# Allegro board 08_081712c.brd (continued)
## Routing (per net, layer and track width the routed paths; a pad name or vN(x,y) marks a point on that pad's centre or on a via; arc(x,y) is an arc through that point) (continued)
GND_FIELD: length 146.9
  L3_SIG w0.508: P2.SH1 249.88,8.46 225.22,8.46 220.42,3.66 214.88,3.66 212.88,5.66 188.34,5.66 185.8,8.2 149.92,8.2 P1.SH2
  BOTTOM w0.508: P1.14 143.04,14.18 ; P1.14 142.12,15.1 ; P1.14 141.19,14.18 ; P1.SH1 129.83,2.88 ; P1.SH1 127.09,2.88 ; P1.SH1 128.46,4.25 ; P2.13 258.86,14.18 ; P2.13 257.93,15.1 ; P2.13 257.01,14.18 ; 143.22,2.88 P1.SH2 ; P1.SH2 145.96,2.88 ; P1.SH2 144.59,4.25 ; P2.14 269.12,15.1 ; P2.14 268.19,14.18 ; P2.14 270.04,14.18 ; 270.22,2.88 P2.SH2 ; P2.SH2 271.59,4.25 ; P2.SH2 272.96,2.88 ; P1.13 130.93,15.1 ; P1.13 131.86,14.18 ; P1.13 130.01,14.18 ; 254.09,2.88 P2.SH1 ; P2.SH1 256.83,2.88 ; P2.SH1 255.46,4.25
VBUS_DETECT: length 12.2
  L8_SIG w0.114: v1(204.21,12.87) 204.21,17.45 204.98,18.22 204.98,18.99 204.77,19.19 204.77,21.04 v2(205.05,21.31)
  BOTTOM w0.305: R481.2 R482.1 204.03,11.82 C345.1
  BOTTOM w0.508: C345.1 v1(204.21,12.87)
VDDIO: length 251
  TOP w0.127: v1(233.95,29.59) 233.96,29.59 234.68,28.87 U66.5
  TOP w0.14: DS23.A v1(228.74,30.45) ; R549.1 v1(240.09,28.37) ; R551.1 v1(232.09,26.47) ; C430.1 v1(188.33,84.68)
  TOP w0.254: U52.16 238.92,90.52 239.15,90.75 239.15,91.12 ; 239.15,84.01 239.15,83.64 238.92,83.41 U15.16 ; 239.15,98.62 239.15,98.24 238.92,98.02 U14.16
  TOP w0.305: C23.1 210.88,89.33 U9.14 ; U75.14 377.64,24.97 C381.1 ; C11.1 262.24,119.07 U51.21 ; C376.1 9.97,24.97 U74.14 ; U8.21 34.28,113.99 C10.1
  TOP w0.381: R434.2 v1(191.13,90.09) ; R436.2 v1(191.13,105.4) ; R432.2 v1(191.13,97.96)
  TOP w0.508: 239.15,98.62 C72.1 v1(238.4,99.06) ; R531.1 v1(205.99,70.8) ; R555.1 v1(336.32,39.47) ; U44.1 341.91,37.81 341.9,37.82 C280.1 C282.1 v1(341.9,39.75) ; R31.1 v1(34.29,109.27) ; v1(214.27,61.92) C9.1 S11.1 ; v1(264.11,119.05) C13.1 C11.1 ; C377.1 v1(16.39,23.9) ; 386.21,113.79 TP16.1 ; TP16.1 386.21,115.57 ; TP16.1 387.98,113.79 ; TP16.1 387.98,115.57 ; C92.1 v1(228.08,109.83) ; R511.2 R510.2 R509.2 v1(23.87,115.51) ; R511.2 v1(23.87,113.22) ; R511.2 R512.2 R513.2 v1(23.87,110.93) ; C263.1 v1(299.46,109.83) ; R435.2 v1(335.98,90.94) ; C170.1 v1(124.2,102.32) ; U42.1 78.99,37.84 78.99,37.85 C271.1 C273.1 v1(78.99,39.78) ; C10.1 C12.1 v1(36.14,113.97) ; R120.1 v1(226,91.43) ; C23.1 v1(211.34,90.7) ; R437.2 v1(335.98,106.69) ; R517.1 v1(385.13,80.78) ; R535.1 v1(84.96,39.5) ; C16.2 103.75,83.59 v1(102.89,83.59) ; v1(93.08,39.78) C272.1 C270.1 93.08,37.85 93.09,37.84 U41.1 ; R32.1 v1(262.25,114.82) ; R433.2 v1(335.98,98.81) ; C168.1 v1(112.96,102.32) ; U43.1 356.01,37.81 356,37.82 C281.1 C283.1 v1(356,39.75) ; v1(238.4,84.45) C73.1 239.15,84.01 ; R554.1 v1(333.78,39.47) ; R585.1 v1(209.84,83.57) ; R543.1 v1(347.87,39.47) ; R462.1 v1(219.01,91.31) ; C91.1 v1(305.81,109.83) ; R540.1 v1(73.4,39.5) ; R536.1 v1(87.5,39.5) ; R544.1 v1(350.41,39.47) ; R528.1 v1(204.47,70.8) ; S15.2 142.16,90.24 C8.1 v1(140.08,89.57) ; 239.15,91.12 C26.1 239.15,92.06 v1(239.67,92.58) ; C381.1 v1(377.56,24.1) ; R514.1 v1(69.79,80.78) ; C376.1 v1(9.9,24.1) ; C265.1 v1(221.73,109.83) ; C369.1 v1(384.06,23.9) ; R539.1 v1(70.86,39.5)
  L5_PWR w0.508: 257.43,25.26 P2.17 ; P2.17 256.31,26.38 ; P2.17 258.55,26.38 ; 386.21,113.79 TP16.1 ; TP16.1 386.21,115.57 ; TP16.1 387.98,115.57 ; TP16.1 387.98,113.79 ; 130.43,25.26 P1.17 ; P1.17 130.43,27.49 ; P1.17 131.55,26.38 ; P1.17 129.31,26.38
  BOTTOM w0.14: v1(213.86,41.86) R24.1 ; C428.1 v1(188.33,82.45)
  BOTTOM w0.178: U65.B4 v1(102.89,83.59) ; U65.D1 105.39,87.97 ; U65.E4 107.82,84.09
  BOTTOM w0.203: U1.31 134.28,46.58 133.98,46.87 ; U2.31 261.28,46.58 260.99,46.87 ; U2.25 v1(259.97,43.19) ; v1(132.97,43.19) U1.25 ; 139.06,46.87 138.77,46.58 U1.40 ; 266.06,46.87 265.77,46.58 U2.40 ; C68.1 252.84,41.59 U12.6 ; C34.1 125.84,41.59 U11.6
  BOTTOM w0.254: v1(406.4,107.57) 402.59,107.57 395.48,114.68 TP16.1 ; U39.16 132.55,95.16 132.8,94.91 132.8,94.44 ; U45.16 127.67,79.97 127.9,79.75 127.9,79.38 ; U48.16 271.18,79.97 271.41,79.75 271.41,79.38 ; U46.16 144.18,79.97 144.41,79.75 144.41,79.38 ; U67.16 11.93,33.12 11.68,33.37 C295.1 ; U62.16 263.05,88.1 263.28,87.88 263.28,87.5 ; U40.16 119.93,98.64 119.67,98.89 119.67,99.37 ; 136.28,87.5 136.28,87.88 136.05,88.1 U61.16 ; 254.9,79.38 254.9,79.75 254.67,79.97 U47.16 ; 115.28,94.44 115.28,94.91 115.02,95.16 U38.16 ; U69.16 379.6,33.12 379.34,33.37 C382.1
  BOTTOM w0.279: C74.1 306.62,104.48 306.74,104.35 U35.16 ; U36.16 218.99,104.35 218.86,104.48 C266.1 ; U37.16 229.02,104.35 228.89,104.48 C75.1 ; U34.16 296.71,104.35 296.58,104.48 C264.1
  BOTTOM w0.305: R546.1 243.4,25.85 243.09,25.54 U64.5 241.43,25.54 C394.1 ; C7.1 224.26,41.4 223.81,41.86 U7.14 ; R548.1 v1(239.99,24.24) ; R547.1 v1(247.56,24.89)
  BOTTOM w0.457: v1(259.97,43.19) v1(259.46,43.19) ; v1(132.46,43.19) v1(132.97,43.19)
  BOTTOM w0.508: 107.82,84.09 107.82,84.09 C15.2 v1(110.39,84.09) ; 271.41,79.38 C293.1 v1(270.66,78.93) ; v1(265.24,56.13) R86.2 R84.2 R103.2 R98.2 259.72,56.13 v1(259.28,56.57) ; R94.2 v1(254.88,41.85) ; R94.2 R113.1 R108.2 R106.2 ; R94.2 R110.1 v1(254.88,40.77) ; U76.4 150.69,82.86 150.18,82.35 C370.1 v1(149.22,83.06) ; v1(138.24,56.13) R54.2 R52.2 R71.2 R66.2 v1(132.4,56.13) ; C394.1 v1(241.42,26.31) ; v1(114.66,94.12) C267.1 115.28,94.44 ; 260.99,46.87 260.72,47.13 C61.1 C59.1 v1(260.72,49.27) 260.72,49.29 v1(260.35,49.66) ; R563.1 v1(283.01,71.89) ; v1(135.53,87.06) C371.1 136.28,87.5 ; C5.1 v1(163.45,30.2) U5.5 ; C382.1 v1(379.34,34.95) ; v1(143.66,78.93) C291.1 144.41,79.38 ; C75.1 v1(228.89,106.19) ; R2.1 v1(150.29,71.89) ; R62.2 R78.1 v1(127.88,40.77) ; R62.2 R81.1 R76.2 R74.2 ; R62.2 v1(127.88,41.85) ; R15.1 v1(292.02,23.19) ; R92.2 R90.2 v1(255.64,51.24) ; R589.1 v1(150.62,77.35) ; 263.28,87.5 C372.1 v1(262.53,87.06) ; R3.1 v1(151.43,71.89) ; R558.1 v1(277.29,71.89) ; R7.1 v1(156.01,71.89) ; R588.1 v1(152.65,77.35) ; R561.1 v1(280.72,71.89) ; C6.1 v1(290.45,30.2) U6.5 ; v1(139.7,49.66) 139.33,49.29 v1(139.33,49.27) C32.1 C42.1 139.33,47.13 139.06,46.87 ; C34.1 v1(126.78,41.74) ; 133.98,46.87 133.72,47.13 C35.1 C33.1 v1(133.72,49.27) 133.72,49.29 v1(133.35,49.66) ; R529.1 v1(279.65,77.27) ; C68.1 v1(253.78,41.74) ; 132.8,94.44 C268.1 v1(132.18,94.12) ; C74.1 v1(306.62,106.19) ; v1(254.15,78.93) C292.1 254.9,79.38 ; R60.2 R58.2 v1(128.64,51.24) ; R33.1 v1(104.39,92.14) ; R530.1 v1(277.62,77.27) ; R560.1 v1(279.58,71.89) ; v1(127.15,78.93) C290.1 127.9,79.38 ; 105.39,87.97 105.39,89.23 C14.2 v1(105.4,90.03) ; R16.1 v1(288.87,23.19) ; v1(276.23,83.06) C24.1 277.18,82.35 277.69,82.86 U10.4 ; R14.1 v1(161.87,23.19) ; C266.1 v1(218.86,106.19) ; C295.1 v1(11.68,34.95) ; C264.1 v1(296.58,106.19) ; R5.1 v1(153.72,71.89) ; v1(120.29,99.68) C269.1 119.67,99.37 ; R562.1 v1(281.86,71.89) ; R21.1 v1(226.19,42.51) ; R13.1 v1(165.02,23.19) ; R6.1 v1(154.86,71.89) ; v1(266.7,49.66) 266.33,49.29 v1(266.33,49.27) C58.1 C60.1 266.33,47.13 266.06,46.87 ; v1(224.29,40.59) C7.1 ; R50.1 v1(99.18,88.79) ; C169.1 v1(120.59,102.32) ; R559.1 v1(278.43,71.89) ; R35.1 v1(99.18,82.41) ; R4.1 v1(152.58,71.89)
  vias: v1(145.15,35.94) v1(145.91,35.94) v1(146.67,36.07) v1(147.44,36.07) v1(182.33,121.72) v1(238.05,30.73) v1(272.1,35.9) v1(272.86,35.9) v1(273.63,36.16) v1(274.39,36.16) v1(384.81,114.94) v1(384.81,114.3) v1(385.44,114.94) v1(385.44,114.3)
24.576MHZ: length 96.9
  TOP w0.127: v1(176.92,130.18) S16.4A S16.3A R126.2
  BOTTOM w0.127: v1(176.92,130.18) 164.34,130.18 143.97,109.8 98.4,109.8 97.33,110.87 P36.1
24.576MHZ_SOMA: length 2.9
  TOP w0.127: U81.2 180.52,126.19 R502.2
24.576MHZ_SOMB: length 2.9
  TOP w0.127: U81.3 180.12,126.2 R503.2
_N11: length 2.1
  TOP w0.127: R83.1 132.97,28.5 P1.18
_N12: length 1.8
  BOTTOM w0.14: U1.10 140.05,41.19 R57.2
_N13: length 6.8
  BOTTOM w0.14: R70.2 137.41,51.31 136.28,50.17 U1.35
_N14: length 6.7
  BOTTOM w0.14: U1.34 135.77,50.94 136.4,51.56 136.4,52.46 R65.2
_N15: length 2.1
  TOP w0.127: R82.1 140.08,28.5 P1.19
_N16: length 6.8
  BOTTOM w0.14: R73.2 129.54,47.2 129.68,47.06 129.85,47.06 129.99,46.92 129.99,46.62 129.85,46.48 129.68,46.48 129.54,46.34 129.54,45.99 129.68,45.85 130.68,45.85 131.34,45.19 U1.29
_N17: length 6.8
  BOTTOM w0.14: R69.2 130.68,46.61 130.9,46.39 131.13,46.39 131.48,46.74 131.67,46.74 131.8,46.61 131.8,45.97 131.96,45.82 132.18,45.82 132.33,45.97 132.33,46.63 132.47,46.77 132.83,46.77 132.97,46.63 132.97,45.85 133.13,45.69 U1.30
_N18: length 6.9
  BOTTOM w0.14: R64.2 133.6,51.18 134.77,50.01 U1.32
_N19: length 6.8
  BOTTOM w0.14: U1.33 135.28,50.91 134.62,51.56 134.62,52.46 R63.2
_N20: length 17.4
  TOP w0.508: P1.6 142.65,21.3 ; P1.6 141.6,22.35 ; P1.6 141.6,20.24 ; 127.63,20.69 C37.1 ; C37.1 128.17,21.27 ; C37.1 127.63,21.86 ; 145.36,23.23 C40.1 ; C40.1 145.36,24.4 ; C40.1 144.81,23.81 ; 130.44,22.78 P1.7 129.38,23.84 ; 143.67,23.84 P1.12 142.62,22.78 ; 145.36,20.69 C41.1 ; C41.1 144.81,21.27 ; C41.1 145.36,21.86 ; 127.63,23.23 C39.1 ; C39.1 128.17,23.81 ; C39.1 127.63,24.4 ; P1.1 131.45,22.35 ; P1.1 131.45,20.24 ; P1.1 130.4,21.3
_N41: length 2.1
  TOP w0.127: P2.18 259.97,28.5 R115.1
_N42: length 1.8
  BOTTOM w0.14: U2.10 267.05,41.19 R89.2
_N43: length 6.8
  BOTTOM w0.14: U2.35 263.28,50.17 264.41,51.31 R102.2
_N44: length 6.7
  BOTTOM w0.14: U2.34 262.77,50.94 263.4,51.56 263.4,52.46 R97.2
_N45: length 2.1
  TOP w0.127: P2.19 267.08,28.5 R114.1
_N46: length 6.8
  BOTTOM w0.14: U2.29 258.34,45.19 257.68,45.85 256.68,45.85 256.54,45.99 256.54,46.34 256.68,46.48 256.85,46.48 256.99,46.62 256.99,46.92 256.85,47.06 256.68,47.06 256.54,47.2 R105.2
_N47: length 6.8
  BOTTOM w0.14: U2.30 260.13,45.69 259.97,45.85 259.97,46.63 259.83,46.77 259.47,46.77 259.33,46.63 259.33,45.97 259.18,45.82 258.96,45.82 258.8,45.97 258.8,46.61 258.67,46.74 258.48,46.74 258.13,46.39 257.9,46.39 257.68,46.61 R101.2
_N48: length 6.9
  BOTTOM w0.14: U2.32 261.77,50.01 260.6,51.18 R96.2
_N49: length 6.8
  BOTTOM w0.14: U2.33 262.28,50.91 261.62,51.56 261.62,52.46 R95.2
_N50: length 17.4
  TOP w0.508: 269.62,22.78 P2.12 270.67,23.84 ; 272.36,23.23 C65.1 ; C65.1 272.36,24.4 ; C65.1 271.81,23.81 ; C66.1 254.63,21.86 ; C66.1 254.63,20.69 ; C66.1 255.17,21.27 ; 256.38,23.84 P2.7 257.44,22.78 ; 254.63,23.23 C67.1 ; C67.1 255.17,23.81 ; C67.1 254.63,24.4 ; 271.81,21.27 C63.1 ; C63.1 272.36,21.86 ; C63.1 272.36,20.69 ; 268.6,20.24 P2.6 ; P2.6 268.6,22.35 ; P2.6 269.65,21.3 ; 257.4,21.3 P2.1 ; P2.1 258.45,22.35 ; P2.1 258.45,20.24
_N448: length 77.2
  L8_SIG w0.127: v1(289.31,32.77) 287.84,34.24 226.47,34.24 221.14,39.57 v1(221.14,43.16)
  BOTTOM w0.127: R20.2 v1(289.31,32.77)
  BOTTOM w0.14: U7.12 v1(221.14,43.16)
_N450: length 9.5
  BOTTOM w0.127: R11.1 293.76,23.24 300.24,23.24 PB3.3
_N451: length 2.2
  BOTTOM w0.127: R12.1 288.01,23.65 PB4.3
_N452: length 2
  BOTTOM w0.127: R20.1 289.5,30.68 U6.4
_N453: length 2
  BOTTOM w0.127: R19.1 291.4,30.68 U6.6
_N454: length 3.9
  BOTTOM w0.127: U6.1 291.11,26.12 291.11,25.55 290.96,25.4 C3.1 R15.2 R11.2
_N455: length 3.9
  BOTTOM w0.127: U6.3 289.79,26.12 289.79,25.55 289.94,25.4 C4.1 R16.2 R12.2
_N552: length 3.3
  TOP w0.508: C137.P 275.64,142.15 R203.2
_N554: length 3.3
  TOP w0.508: R204.2 267.66,142.15 C138.P
_N555: length 5.6
  TOP w0.508: R194.1 C130.N
_N556: length 5.6
  TOP w0.508: R188.1 C129.N
_N557: length 3.3
  TOP w0.508: R173.2 334.32,142.15 C121.P
_N558: length 5.6
  TOP w0.508: R166.1 C116.N
_N559: length 3.3
  TOP w0.508: C122.P 326.34,142.15 R174.2
_N560: length 3.3
  TOP w0.508: C123.P 315.27,142.15 R175.2
_N561: length 3.3
  TOP w0.508: R176.2 307.29,142.15 C124.P
_N562: length 5.6
  TOP w0.508: R160.1 C115.N
_N563: length 3.3
  TOP w0.508: C135.P 294.69,142.15 R201.2
_N566: length 3.3
  TOP w0.508: R202.2 286.71,142.15 C136.P
_N568: length 3.4
  TOP w0.508: R189.2 287.77,151.97 R190.2 288.16,150.74 U24.5
_N569: length 6.7
  TOP w0.508: R198.1 285.56,148.21 U24.6 ; R198.1 283.61,148.52 C132.1 ; R198.1 R188.2
_N570: length 8.2
  TOP w0.508: C133.2 278.74,145.35 R199.2 276.8,145.67 U25.1 272.92,145.67 272.42,145.16 R203.1
_N571: length 8.5
  TOP w0.508: R192.2 274.58,151.97 R193.2 272.54,151.13 272.18,150.77 272.18,148.57 272.54,148.21 U25.3
_N572: length 7.9
  TOP w0.508: R199.1 278.74,147.25 C133.1 ; R199.1 276.8,146.94 U25.2 ; R199.1 R191.2
_N574: length 3.4
  TOP w0.508: R195.2 268.72,151.97 R196.2 269.11,150.74 U25.5
_N575: length 6.7
  TOP w0.508: U25.6 266.51,148.21 R200.1 ; R200.1 R194.2 ; R200.1 264.56,148.52 C134.1
_N577: length 7.9
  TOP w0.508: C117.1 337.42,147.25 R169.1 ; R169.1 R157.2 ; R169.1 335.47,146.94 U22.2
_N578: length 8.5
  TOP w0.508: R158.2 333.26,151.97 R159.2 331.22,151.13 330.86,150.77 330.86,148.57 331.22,148.21 U22.3
_N580: length 3.4
  TOP w0.508: R161.2 327.4,151.97 R162.2 327.79,150.74 U22.5
_N581: length 6.7
  TOP w0.508: U22.6 325.18,148.21 R170.1 ; R170.1 323.24,148.52 C118.1 ; R170.1 R160.2
_N582: length 8.2
  TOP w0.508: R175.1 312.04,145.16 312.55,145.67 U23.1 316.42,145.67 R171.2 318.37,145.35 C119.2
_N583: length 8.5
  TOP w0.508: R164.2 314.21,151.97 R165.2 312.17,151.13 311.81,150.77 311.81,148.57 312.17,148.21 U23.3
_N584: length 7.9
  TOP w0.508: R171.1 316.42,146.94 U23.2 ; R171.1 R163.2 ; R171.1 318.37,147.25 C119.1
_N586: length 3.4
  TOP w0.508: R167.2 308.35,151.97 R168.2 308.74,150.74 U23.5
_N587: length 6.7
  TOP w0.508: R172.1 R166.2 ; R172.1 306.13,148.21 U23.6 ; R172.1 304.19,148.52 C120.1
_N588: length 8.2
  TOP w0.508: R201.1 291.47,145.16 291.97,145.67 U24.1 295.85,145.67 R197.2 297.79,145.35 C131.2
_N589: length 8.5
  TOP w0.508: R186.2 293.63,151.97 R187.2 291.59,151.13 291.23,150.77 291.23,148.57 291.59,148.21 U24.3
_N590: length 7.9
  TOP w0.508: R197.1 295.85,146.94 U24.2 ; R197.1 R185.2 ; R197.1 297.79,147.25 C131.1
_N672: length 3.3
  TOP w0.508: R259.2 197.92,142.15 C165.P
_N674: length 3.3
  TOP w0.508: R260.2 189.94,142.15 C166.P
_N675: length 5.6
  TOP w0.508: R250.1 C158.N
_N676: length 5.6
  TOP w0.508: R244.1 C157.N
_N677: length 3.3
  TOP w0.508: R229.2 256.59,142.15 C149.P
_N678: length 5.6
  TOP w0.508: R222.1 C144.N
_N679: length 3.3
  TOP w0.508: R230.2 248.61,142.15 C150.P
_N680: length 3.3
  TOP w0.508: R231.2 237.54,142.15 C151.P
_N681: length 3.3
  TOP w0.508: C152.P 229.56,142.15 R232.2
_N682: length 5.6
  TOP w0.508: R216.1 C143.N
_N683: length 3.3
  TOP w0.508: R257.2 216.97,142.15 C163.P
_N686: length 3.3
  TOP w0.508: R258.2 208.99,142.15 C164.P
_N688: length 3.4
  TOP w0.508: U28.5 210.44,150.74 R246.2 210.05,151.97 R245.2
_N689: length 6.7
  TOP w0.508: U28.6 207.83,148.21 R254.1 ; R254.1 205.89,148.52 C160.1 ; R254.1 R244.2
_N690: length 8.2
  TOP w0.508: R259.1 194.69,145.16 195.2,145.67 U29.1 199.08,145.67 R255.2 201.02,145.35 C161.2
_N691: length 8.5
  TOP w0.508: U29.3 194.82,148.21 194.46,148.57 194.46,150.77 194.82,151.13 R249.2 196.86,151.97 R248.2
_N692: length 7.9
  TOP w0.508: R255.1 199.08,146.94 U29.2 ; R255.1 201.02,147.25 C161.1 ; R255.1 R247.2
_N694: length 3.4
  TOP w0.508: U29.5 191.39,150.74 R252.2 191,151.97 R251.2
_N695: length 6.7
  TOP w0.508: U29.6 188.78,148.21 R256.1 ; R256.1 R250.2 ; R256.1 186.84,148.52 C162.1
_N696: length 8.2
  TOP w0.508: R229.1 253.36,145.16 253.87,145.67 U26.1 257.75,145.67 R225.2 259.69,145.35 C145.2
_N697: length 7.9
  TOP w0.508: R225.1 257.75,146.94 U26.2 ; R225.1 259.69,147.25 C145.1 ; R225.1 R213.2
_N698: length 8.5
  TOP w0.508: R214.2 255.53,151.97 R215.2 253.49,151.13 253.13,150.77 253.13,148.57 253.49,148.21 U26.3
_N700: length 3.4
  TOP w0.508: U26.5 250.06,150.74 R218.2 249.67,151.97 R217.2
_N701: length 6.7
  TOP w0.508: R226.1 R216.2 ; R226.1 247.46,148.21 U26.6 ; R226.1 245.51,148.52 C146.1
_N702: length 8.2
  TOP w0.508: C147.2 240.64,145.35 R227.2 238.7,145.67 U27.1 234.82,145.67 234.31,145.16 R231.1
_N703: length 8.5
  TOP w0.508: U27.3 234.44,148.21 234.08,148.57 234.08,150.77 234.44,151.13 R221.2 236.48,151.97 R220.2
_N704: length 7.9
  TOP w0.508: R227.1 238.7,146.94 U27.2 ; R227.1 R219.2 ; R227.1 240.64,147.25 C147.1
_N706: length 3.4
  TOP w0.508: R223.2 230.62,151.97 R224.2 231.01,150.74 U27.5
_N707: length 6.7
  TOP w0.508: R228.1 228.41,148.21 U27.6 ; R228.1 226.46,148.52 C148.1 ; R228.1 R222.2
_N708: length 8.2
  TOP w0.508: C159.2 220.07,145.35 R253.2 218.13,145.67 U28.1 214.25,145.67 213.74,145.16 R257.1
_N709: length 8.5
  TOP w0.508: U28.3 213.87,148.21 213.51,148.57 213.51,150.77 213.87,151.13 R243.2 215.91,151.97 R242.2
_N710: length 7.9
  TOP w0.508: R253.1 220.07,147.25 C159.1 ; R253.1 218.13,146.94 U28.2 ; R253.1 R241.2
_N761: length 3.2
  TOP w0.305: R438.1 395.99,152.74 396.3,153.04 U49.4
_N762: length 3
  TOP w0.305: U49.3 395.41,153.54 C294.1
_N764: length 3.5
  TOP w0.305: U49.7 403.3,153.04 403.61,152.74 C301.1
_N765: length 7.2
  TOP w0.305: C304.1 406.9,150.37 R446.1 405.38,150.5 402.07,150.5 R444.1 401.52,151.05 U49.6
_N766: length 3.2
  TOP w0.305: R442.1 403.99,153.54 U49.8
_N778: length 7.8
  TOP w0.305: U33.24 103.85,112.81 103.5,112.46 103.5,111.63
  TOP w0.508: 103.5,111.63 103.5,109.86 103.89,109.48 R284.2 Q1.1
_N780: length 25.3
  TOP w0.203: C174.2 97.77,117.75 C175.1 R280.2
  TOP w0.305: 101.22,111.31 101.85,111.94 102.27,111.94 103.2,112.88 U33.23 ; U33.41 v1(117.04,115.49) ; U33.20 v1(99.11,115.49) ; C174.2 98.69,117.61 99.17,118.09 U33.16 ; U33.29 v1(107.1,112.7)
  TOP w0.508: Q1.4 Q1.2 v1(102.36,108.81) C179.1 101.73,109.48 101.22,109.99 101.22,111.31 ; C174.2 v1(97.92,116.86)
  BOTTOM w0.508: v1(102.36,108.81) 102.36,107.76 C180.1
_N784: length 5
  TOP w0.305: C181.1 113.6,130.63 U33.62
  TOP w0.508: C181.1 v1(115.6,131.83)
  BOTTOM w0.508: C182.1 115.6,131.1 v1(115.6,131.83)
_N787: length 4.6
  TOP w0.305: C183.1 112.95,131.63 U33.63
  TOP w0.508: C183.1 v1(113.94,131.83)
  BOTTOM w0.508: v1(113.94,131.83) 113.94,131.15 C186.1
_N789: length 3.4
  TOP w0.305: C188.1 99.19,128.99 99.19,128.27 99.62,127.84 U33.1
_N790: length 3.4
  TOP w0.305: C191.1 116.97,128.99 116.97,128.27 116.54,127.84 U33.60
_N791: length 2.6
  TOP w0.305: C193.2 99.29,127.19 U33.2
_N792: length 2.6
  TOP w0.305: U33.59 116.87,127.19 C190.2
_N798: length 2.4
  TOP w0.305: R283.1 117.99,118.74 U33.46
_N799: length 2.6
  TOP w0.305: R282.1 118.11,117.47 117.49,118.09 U33.45
_N800: length 2.5
  TOP w0.305: R278.1 117.67,116.14 U33.42
_N829: length 80.6
  L8_SIG w0.127: v1(221.42,45.11) 222.25,44.28 222.25,39.2 226.71,34.75 289.62,34.75 290.45,33.91 v1(291.59,32.77)
  BOTTOM w0.127: R19.2 v1(291.59,32.77)
  BOTTOM w0.14: U7.9 v1(221.42,45.11)
_N831: length 1.9
  TOP w0.14: R359.1 v1(87.38,23.5) R358.2
  BOTTOM w0.508: C278.1 v1(87.38,23.5)
_N832: length 36
  TOP w0.14: R359.2 U41.12
  TOP w0.254: v1(84.54,6.33) 84.54,8.09 88.01,11.56 90.68,11.56 93.09,13.97 93.09,17.91 88.77,22.23 88.77,24.25 88.52,24.5 R359.2
  BOTTOM w0.305: P18.1_7 79.11,6.73 82.91,6.73 83.36,7.18 84.54,7.18 D5.2 v1(84.54,6.33)
_N833: length 32
  TOP w0.14: R358.1 U41.11
  TOP w0.254: R358.1 86.23,24.5 85.98,24.25 85.98,21.59 88.26,19.3 89.92,19.3 91.83,17.39 91.83,14.74 90.04,12.95 87.58,12.95 85.07,10.44 v1(84.54,9.92)
  BOTTOM w0.305: v1(84.54,9.92) D5.1 83.36,9.07 82.91,9.52 80.55,9.52 P18.1_2
_N836: length 5.7
  TOP w0.14: R356.1 82.93,27.79 83.44,28.3 84.96,28.3 85.47,27.79 U41.10
_N863: length 1.9
  TOP w0.14: R360.2 v1(73.28,23.5) R361.1
  BOTTOM w0.508: C279.1 v1(73.28,23.5)
_N864: length 32.6
  TOP w0.14: R361.2 U42.12
  TOP w0.254: R361.2 74.43,24.5 74.68,24.26 74.68,21.59 75.31,20.96 83.82,20.96 85.85,18.92 85.85,14.37 v1(84.54,13.07)
  BOTTOM w0.305: v1(84.54,13.07) D6.2 83.36,13.92 82.91,13.46 79.14,13.46 P18.2_7
_N865: length 28.5
  TOP w0.14: R360.1 U42.11
  TOP w0.254: v1(84.54,16.65) 84.54,18.33 83.31,19.56 73.41,19.56 71.88,21.08 71.88,24.25 72.14,24.5 R360.1
  BOTTOM w0.305: P18.2_2 80.55,16.28 82.91,16.28 83.39,15.8 D6.1 v1(84.54,16.65)
_N866: length 2.8
  BOTTOM w0.305: P18.2_9 69.46,14.83 R363.2
_N867: length 5.7
  TOP w0.14: R357.1 68.83,27.79 69.34,28.3 70.87,28.3 71.37,27.79 U42.10
_N873: length 2.8
  BOTTOM w0.305: R362.2 69.48,8.08 P18.1_9
_N894: length 1.9
  TOP w0.14: R366.2 v1(350.29,23.48) R367.1
  BOTTOM w0.508: C288.1 v1(350.29,23.48)
_N895: length 36
  TOP w0.14: R367.2 U43.12
  TOP w0.254: v1(347.46,6.31) 347.46,8.06 350.93,11.53 353.59,11.53 356.01,13.94 356.01,17.88 351.69,22.2 351.69,24.22 351.43,24.48 R367.2
  BOTTOM w0.305: P19.1_7 342.03,6.7 345.82,6.7 346.27,7.16 347.46,7.16 D7.2 v1(347.46,6.31)
_N896: length 32
  TOP w0.14: R366.1 U43.11
  TOP w0.254: R366.1 349.15,24.48 348.89,24.22 348.89,21.56 351.18,19.28 352.83,19.28 354.74,17.37 354.74,14.71 352.96,12.93 350.5,12.93 347.99,10.42 v1(347.46,9.89)
  BOTTOM w0.305: P19.1_2 343.46,9.5 345.82,9.5 346.28,9.04 D7.1 v1(347.46,9.89)
_N897: length 5.7
  TOP w0.14: U43.10 348.39,27.77 347.88,28.28 346.35,28.28 345.85,27.77 R364.1
_N898: length 1.9
  TOP w0.14: R369.1 v1(336.19,23.48) R368.2
  BOTTOM w0.508: C289.1 v1(336.19,23.48)
_N899: length 32.6
  TOP w0.14: R369.2 U44.12
  TOP w0.254: R369.2 337.35,24.48 337.59,24.23 337.59,21.56 338.23,20.93 346.74,20.93 348.77,18.9 348.77,14.35 v1(347.46,13.04)
  BOTTOM w0.305: P19.2_7 342.05,13.43 345.82,13.43 346.28,13.89 D8.2 v1(347.46,13.04)
_N900: length 28.5
  TOP w0.14: R368.1 U44.11
  TOP w0.254: v1(347.46,16.62) 347.46,18.3 346.23,19.53 336.32,19.53 334.8,21.06 334.8,24.22 335.05,24.48 R368.1
  BOTTOM w0.305: P19.2_2 343.46,16.25 345.82,16.25 346.3,15.77 D8.1 v1(347.46,16.62)
_N901: length 2.8
  BOTTOM w0.305: P19.2_9 332.37,14.81 R371.2
_N902: length 5.7
  TOP w0.14: R365.1 331.75,27.77 332.26,28.28 333.78,28.28 334.29,27.77 U44.10
_N903: length 2.8
  BOTTOM w0.305: R370.2 332.4,8.05 P19.1_9
_N916: length 11.2
  TOP w0.114: R268.1 108.99,106.66 113.68,106.66 114.66,105.68 U30.10
_N917: length 10.9
  TOP w0.114: R270.1 107.31,108.98 109.24,107.06 113.92,107.06 115.06,105.92 U30.9
_N918: length 5.5
  TOP w0.114: R272.1 114.17,107.44 115.46,106.15 U30.8
_N919: length 6.5
  TOP w0.114: U30.7 115.86,106.64 v1(115.44,107.06)
  TOP w0.127: R275.1 v1(113.03,108.71)
  BOTTOM w0.114: v1(115.44,107.06) 113.8,108.71 v1(113.03,108.71)
_N920: length 3.7
  TOP w0.14: R268.2 106.17,112.26 105.8,112.63 U33.27
_N921: length 3.9
  TOP w0.14: R270.2 107.31,111.69 106.45,112.56 U33.28
_N922: length 4
  TOP w0.14: U33.38 112.95,111.7 R272.2
_N923: length 3.8
  TOP w0.14: U33.37 112.3,111.21 R275.2
_N935: length 10.2
  TOP w0.127: R274.1 v1(111.89,108.71)
  BOTTOM w0.114: v1(111.89,108.71) 112.52,108.08 113.67,108.08 115.19,106.55 118.11,106.55 118.89,105.77 U31.10
_N937: length 11.4
  TOP w0.127: R277.1 v1(109.6,108.71)
  BOTTOM w0.114: U31.8 118.09,105.3 117.6,105.79 114.68,105.79 113.16,107.31 110.99,107.31 v1(109.6,108.71)
_N938: length 12
  TOP w0.127: R279.1 v1(108.46,108.71)
  BOTTOM w0.114: v1(108.46,108.71) 110.23,106.93 112.9,106.93 114.43,105.41 117.35,105.41 117.69,105.07 U31.7
_N939: length 18.2
  TOP w0.14: U32.10 125.84,104.92 v1(125.38,105.39) 125.38,106.01 R271.2
  TOP w0.305: U33.43 v1(117.33,116.79)
  L3_SIG w0.127: v1(125.38,105.39) 125.38,107.92 117.98,115.32 117.98,116.14 v1(117.33,116.79)
_N940: length 19.3
  TOP w0.14: U32.9 v1(126.24,105.39) 126.24,106.03 R273.2
  TOP w0.305: U33.44 v1(117.04,117.44)
  L3_SIG w0.127: v1(117.04,117.44) 117.76,117.44 118.87,116.33 118.87,115.57 126.24,108.2 v1(126.24,105.39)
_N942: length 10.8
  TOP w0.127: R276.1 v1(110.74,108.71)
  BOTTOM w0.114: v1(110.74,108.71) 111.76,107.7 113.41,107.7 114.94,106.17 117.86,106.17 118.49,105.54 U31.9
_N943: length 3.6
  TOP w0.14: R274.2 111.65,110.72 U33.36
_N944: length 3.6
  TOP w0.14: U33.35 111,110.74 R276.2
_N945: length 4
  TOP w0.14: R279.2 109.7,111.73 U33.33
_N946: length 3.8
  TOP w0.14: U33.34 110.35,111.23 R277.2
_N948: length 22.3
  TOP w0.14: U32.7 127.04,104.79 127.27,105.03 127.79,105.03 v1(128.14,105.39) R269.2
  TOP w0.305: U33.47 v1(117.04,119.39)
  L3_SIG w0.127: v1(117.04,119.39) 128.14,108.29 v1(128.14,105.39)
_N956: length 3.6
  TOP w0.203: C176.1 97.05,118.61 C174.1 98.05,118.74 U33.15
_N957: length 4.8
  TOP w0.508: C176.2 94.74,118.77 94.23,118.26 94.23,117.22 94.74,116.71 R280.1
_N962: length 7.1
  TOP w0.508: R289.2 133.68,109.56 C203.1 137.56,109.56 C399.1 138.95,109.67 C211.P
_N965: length 4.2
  TOP w0.305: U18.3 297.2,122.92 296.43,123.69
  TOP w0.508: 296.43,123.69 C87.2 295.14,123.7 R151.2
_N982: length 1
  TOP w0.508: C83.2 R151.1
_N983: length 5.5
  TOP w0.305: C79.1 296.84,119.42 U18.10
  TOP w0.508: C79.1 294.88,118.86 C81.1 294.4,118.86 R149.1
_N985: length 10.2
  TOP w0.305: C95.1 296.16,124.84 297.59,123.42 U18.2
  TOP w0.508: C95.1 295.39,124.85 295.03,125.21 C99.1 291.95,125.21 C103.1 291.05,125.32 290.64,124.9 A1.3
_N988: length 3.3
  TOP w0.14: U18.13 299.74,115.81 R145.1
_N989: length 3.5
  TOP w0.14: U18.14 300.24,116.45 R141.1
_N990: length 3.9
  TOP w0.14: R146.1 301.63,116.2 301.37,116.2 300.74,116.84 U18.15
_N991: length 4.4
  TOP w0.14: U18.16 301.24,117.23 302.26,116.2 302.77,116.2 R142.1
_N992: length 3
  TOP w0.14: U20.7 302.3,112.69 303.42,113.8 R142.2
_N993: length 2.7
  TOP w0.14: R146.2 302.27,113.55 301.9,113.18 U20.8
_N994: length 2.7
  TOP w0.14: R141.2 301.13,113.53 301.5,113.16 U20.9
_N995: length 3
  TOP w0.14: U20.10 301.1,112.67 301.08,112.69 301.08,112.71 299.99,113.8 R145.2
_N996: length 12.2
  TOP w0.14: v1(303.02,116.97) 302.25,117.74 302.25,118.05 302.24,118.06 U18.18 ; U16.8 308.25,113.04 v1(308.99,113.79) R127.2
  BOTTOM w0.203: v1(303.02,116.97) 304.8,115.19 307.59,115.19 v1(308.99,113.79)
_N997: length 14.8
  TOP w0.14: U18.17 301.74,117.44 v1(302.24,116.95) ; U16.7 308.65,112.3 v1(310.13,113.79) R129.2
  BOTTOM w0.203: v1(310.13,113.79) 308.22,115.7 305.05,115.7 303.28,117.47 302.77,117.47 v1(302.24,116.95)
_N998: length 19.2
  TOP w0.14: R131.1 v1(307.85,113.79) U16.9 ; v1(296.16,120.98) 297,120.98 297.44,121.42 U18.6
  BOTTOM w0.203: v1(307.85,113.79) 306.95,114.68 302.46,114.68 v1(296.16,120.98)
_N1002: length 2.9
  TOP w0.14: R133.1 295.24,119.92 U18.9
_N1003: length 3.9
  TOP w0.14: R137.1 303.66,116.46 303.66,117.09 302.74,118.01 U18.19
_N1004: length 4.2
  TOP w0.14: U18.20 303.24,118.27 304.29,117.22 304.29,116.97 R139.1
_N1005: length 3.4
  TOP w0.14: R135.2 295.15,121.08 295.84,120.4 297.05,120.4 297.57,120.92 U18.7
_N1045: length 4.2
  TOP w0.305: U19.3 219.48,122.92 218.7,123.69
  TOP w0.508: 218.7,123.69 C88.2 217.42,123.7 R152.2
_N1046: length 1
  TOP w0.508: C84.2 R152.1
_N1047: length 5.5
  TOP w0.305: U19.10 219.12,119.42 C80.1
  TOP w0.508: R150.1 216.68,118.86 C82.1 217.15,118.86 C80.1
_N1048: length 10.2
  TOP w0.305: C96.1 218.44,124.84 219.87,123.42 U19.2
  TOP w0.508: A2.3 212.91,124.9 213.33,125.32 C104.1 214.23,125.21 C100.1 217.31,125.21 217.67,124.85 C96.1
_N1049: length 3.3
  TOP w0.14: R147.1 222.02,115.81 U19.13
_N1050: length 3.5
  TOP w0.14: R143.1 222.52,116.45 U19.14
_N1051: length 3.9
  TOP w0.14: R148.1 223.91,116.2 223.65,116.2 223.02,116.84 U19.15
_N1052: length 4.4
  TOP w0.14: U19.16 223.52,117.23 224.54,116.2 225.05,116.2 R144.1
_N1053: length 3
  TOP w0.14: U21.7 224.57,112.69 225.69,113.8 R144.2
_N1054: length 2.7
  TOP w0.14: U21.8 224.17,113.18 224.55,113.55 R148.2
_N1055: length 2.7
  TOP w0.14: U21.9 223.77,113.16 223.41,113.53 R143.2
_N1056: length 3
  TOP w0.14: U21.10 223.37,112.67 223.35,112.69 223.35,112.71 222.26,113.8 R147.2
_N1057: length 12.2
  TOP w0.14: v1(225.3,116.97) 224.52,117.74 224.52,118.05 224.52,118.06 U19.18 ; R128.2 v1(231.27,113.79) 230.52,113.04 U17.8
  BOTTOM w0.203: v1(225.3,116.97) 227.08,115.19 229.87,115.19 v1(231.27,113.79)
_N1058: length 14.8
  TOP w0.14: U19.17 224.02,117.44 v1(224.51,116.95) ; R130.2 v1(232.41,113.79) 230.92,112.3 U17.7
  BOTTOM w0.203: v1(224.51,116.95) 225.04,117.47 225.55,117.47 227.33,115.7 230.5,115.7 v1(232.41,113.79)
_N1059: length 19.2
  TOP w0.14: U17.9 v1(230.12,113.79) R132.1 ; U19.6 219.71,121.42 219.27,120.98 v1(218.44,120.98)
  BOTTOM w0.203: v1(218.44,120.98) 224.73,114.68 229.23,114.68 v1(230.12,113.79)
_N1060: length 2.9
  TOP w0.14: U19.9 217.52,119.92 R134.1
_N1061: length 3.9
  TOP w0.14: U19.19 225.02,118.01 225.93,117.09 225.93,116.46 R138.1
_N1062: length 4.2
  TOP w0.14: R140.1 226.57,116.97 226.57,117.22 225.52,118.27 U19.20
_N1063: length 3.4
  TOP w0.14: U19.7 219.85,120.92 219.33,120.4 218.12,120.4 217.43,121.08 R136.2
_N1086: length 7
  TOP w0.203: P36.2 96.89,114.67 R281.2 97.1,115.82 97.79,115.82 99.41,117.44 U33.17
_N1090: length 1.8
  TOP w0.14: R265.2 126.64,101.93 U32.4
_N1095: length 2.2
  TOP w0.14: R123.2 307.45,110.08 U16.2
_N1105: length 7.1
  TOP w0.508: C212.P 138.95,111.47 C399.2 137.56,111.57 C204.1 133.68,111.57 R290.2
_N1117: length 5.9
  TOP w0.127: R392.1 227.08,38.54 R384.2 227.08,38.55 R376.2
_N1122: length 5.9
  TOP w0.127: R377.2 228.22,38.55 R386.2 228.22,38.54 R393.1
_N1134: length 5.9
  TOP w0.127: R372.2 R388.1
_N1138: length 5.9
  TOP w0.127: R373.2 R389.1
_N1142: length 5.9
  TOP w0.127: R374.2 R390.1
_N1146: length 5.9
  TOP w0.127: R375.2 R391.1
_N1196: length 5.9
  TOP w0.127: R382.2 235.46,38.55 R385.2 235.46,38.54 R398.1
_N1197: length 5.9
  TOP w0.127: R399.1 236.61,35.62 R387.2 236.6,38.55 R383.2
_N1198: length 5.9
  TOP w0.127: R378.2 R394.1
_N1199: length 5.9
  TOP w0.127: R379.2 R395.1
_N1200: length 5.9
  TOP w0.127: R380.2 R396.1
_N1201: length 5.9
  TOP w0.127: R381.2 R397.1
_N1233: length 3.3
  TOP w0.127: SOMA.111 v1(141.64,64.78)
  BOTTOM w0.127: R1.2 141.64,62.98 v1(141.64,64.78)
_N1244: length 7.1
  TOP w0.508: R291.2 133.68,118.2 C205.1 137.56,118.2 C400.1 138.95,118.3 C213.P
_N1245: length 7.1
  TOP w0.508: C214.P 138.95,120.1 C400.2 137.56,120.21 C206.1 133.68,120.21 R292.2
_N1250: length 7.1
  TOP w0.508: C207.P 138.95,126.94 C401.1 137.56,126.83 C199.1 133.68,126.83 R285.2
_N1251: length 7.1
  TOP w0.508: C208.P 138.95,128.74 C401.2 137.56,128.84 C200.1 133.68,128.84 R286.2
_N1256: length 7.1
  TOP w0.508: C209.P 138.95,135.57 C402.1 137.56,135.47 C201.1 133.68,135.47 R287.2
_N1257: length 7.1
  TOP w0.508: C210.P 138.95,137.37 C402.2 137.56,137.48 C202.1 133.68,137.48 R288.2
_N1276: length 7.1
  TOP w0.508: C227.P 138.56,153.3 C403.1 138.66,151.91 C219.1 138.66,148.03 R305.2
_N1277: length 7.1
  TOP w0.508: R306.2 136.65,148.03 C220.1 136.65,151.91 C403.2 136.76,153.3 C228.P
_N1278: length 7.1
  TOP w0.508: C229.P 129.92,153.3 C404.1 130.03,151.91 C221.1 130.03,148.03 R307.2
_N1279: length 7.1
  TOP w0.508: R308.2 128.02,148.03 C222.1 128.02,151.91 C404.2 128.12,153.3 C230.P
_N1280: length 7.1
  TOP w0.508: R301.2 121.39,148.03 C215.1 121.39,151.91 C405.1 121.29,153.3 C223.P
_N1281: length 7.1
  TOP w0.508: C224.P 119.49,153.3 C405.2 119.38,151.91 C216.1 119.38,148.03 R302.2
_N1282: length 7.1
  TOP w0.508: C225.P 112.65,153.3 C406.1 112.75,151.91 C217.1 112.75,148.03 R303.2
_N1283: length 7.1
  TOP w0.508: C226.P 110.85,153.3 C406.2 110.74,151.91 C218.1 110.74,148.03 R304.2
_N1300: length 7.1
  TOP w0.508: C243.P 104.01,153.3 C407.1 104.12,151.91 C235.1 104.12,148.03 R321.2
_N1301: length 7.1
  TOP w0.508: C244.P 102.21,153.3 C407.2 102.11,151.91 C236.1 102.11,148.03 R322.2
_N1302: length 7.1
  TOP w0.508: R323.2 95.48,148.03 C237.1 95.48,151.91 C408.1 95.38,153.3 C245.P
_N1303: length 7.1
  TOP w0.508: C246.P 93.58,153.3 C408.2 93.47,151.91 C238.1 93.47,148.03 R324.2
_N1304: length 7.1
  TOP w0.508: C239.P 86.74,153.3 C409.1 86.85,151.91 C231.1 86.85,148.03 R317.2
_N1305: length 7.1
  TOP w0.508: C240.P 84.94,153.3 C409.2 84.84,151.91 C232.1 84.84,148.03 R318.2
_N1306: length 7.1
  TOP w0.508: C241.P 78.11,153.3 C410.1 78.21,151.91 C233.1 78.21,148.03 R319.2
_N1307: length 7.1
  TOP w0.508: R320.2 76.2,148.03 C234.1 76.2,151.91 C410.2 76.31,153.3 C242.P
_N1324: length 7.1
  TOP w0.508: R333.2 82.48,137.48 C247.1 78.59,137.48 C411.1 77.21,137.37 C251.P
_N1325: length 7.1
  TOP w0.508: C252.P 77.21,135.57 C411.2 78.59,135.47 C248.1 82.48,135.47 R334.2
_N1326: length 7.1
  TOP w0.508: R335.2 82.48,128.84 C249.1 78.59,128.84 C412.1 77.21,128.74 C253.P
_N1327: length 7.1
  TOP w0.508: R336.2 82.48,126.83 C250.1 78.59,126.83 C412.2 77.21,126.94 C254.P
_N1336: length 7.1
  TOP w0.508: R341.2 82.48,120.21 C255.1 78.59,120.21 C413.1 77.21,120.1 C259.P
_N1337: length 7.1
  TOP w0.508: C260.P 77.21,118.3 C413.2 78.59,118.2 C256.1 82.48,118.2 R342.2
_N1338: length 7.1
  TOP w0.508: C261.P 77.21,111.47 C414.1 78.59,111.57 C257.1 82.48,111.57 R343.2
_N1339: length 7.1
  TOP w0.508: C262.P 77.21,109.67 C414.2 78.59,109.56 C258.1 82.48,109.56 R344.2
_N1376: length 8.2
  TOP w0.508: R173.1 331.09,145.16 331.6,145.67 U22.1 335.47,145.67 R169.2 337.42,145.35 C117.2
_N1392: length 6.7
  TOP w0.508: S3.1 335.71,157.69 C113.N
_N1393: length 7.3
  TOP w0.508: S3.2 331.78,155.45 335.28,155.45 335.79,154.94 R157.1
_N1395: length 6.7
  TOP w0.508: S4.1 316.66,157.69 C114.N
_N1396: length 7.3
  TOP w0.508: R163.1 316.74,154.94 316.23,155.45 312.73,155.45 S4.2
_N1398: length 6.7
  TOP w0.508: S5.1 296.09,157.69 C127.N
_N1399: length 7.3
  TOP w0.508: R185.1 296.16,154.94 295.66,155.45 292.16,155.45 S5.2
_N1401: length 6.7
  TOP w0.508: C128.N 277.04,157.69 S6.1
_N1402: length 7.3
  TOP w0.508: R191.1 277.11,154.94 276.61,155.45 273.11,155.45 S6.2
_N1404: length 6.7
  TOP w0.508: C141.N 257.99,157.69 S7.1
_N1405: length 7.3
  TOP w0.508: S7.2 254.06,155.45 257.56,155.45 258.06,154.94 R213.1
_N1407: length 6.7
  TOP w0.508: S8.1 238.94,157.69 C142.N
_N1408: length 7.3
  TOP w0.508: R219.1 239.01,154.94 238.51,155.45 235.01,155.45 S8.2
_N1410: length 7.3
  TOP w0.508: R241.1 218.44,154.94 217.93,155.45 214.43,155.45 S9.2
_N1411: length 6.7
  TOP w0.508: C155.N 218.37,157.69 S9.1
_N1413: length 6.7
  TOP w0.508: S10.1 199.32,157.69 C156.N
_N1414: length 7.3
  TOP w0.508: R247.1 199.39,154.94 198.88,155.45 195.38,155.45 S10.2
_N1418: length 1.4
  BOTTOM w0.14: R349.1 295.84,103.85 U34.15
_N1461: length 1.4
  BOTTOM w0.203: R350.1 305.87,103.85 U35.15
_N1496: length 1.4
  BOTTOM w0.14: U36.15 218.12,103.85 R351.1
_N1497: length 1.4
  BOTTOM w0.203: R352.1 228.15,103.85 U37.15
_N1508: length 1.4
  BOTTOM w0.127: R353.1 U38.15
_N1509: length 1.4
  BOTTOM w0.127: U39.15 R354.1
_N1534: length 1.5
  BOTTOM w0.127: U40.15 R355.1
_N1575: length 6.3
  BOTTOM w0.14: R56.1 142.35,41.53 143.82,40.07 143.82,37.91 144.16,37.57 Y1.3
_N1581: length 1.4
  BOTTOM w0.127: U45.15 128.51,80.47 R408.1
_N1583: length 139.3
  L3_SIG w0.127: v1(122.56,80.7) 123.7,79.55 131.83,79.55 133.11,78.27 142.39,78.27 143.01,77.65 146.27,77.65 147.79,79.17 149.7,79.17 149.74,79.22 149.75,79.22 150.51,79.98 154.2,79.98 157.86,83.64 193.32,83.64 196.21,80.75 211.48,80.75 217.8,74.42 239.95,74.42 246.23,80.7 v1(249.55,80.7)
  BOTTOM w0.127: U45.2 122.78,80.47 v1(122.56,80.7) ; v1(249.55,80.7) 249.78,80.47 U47.2
_N1584: length 140.1
  L3_SIG w0.127: v1(249.59,82.23) 247.26,82.23 239.96,74.93 217.91,74.93 211.65,81.19 196.46,81.19 193.62,84.04 157.75,84.04 154.05,80.34 150.37,80.34 149.6,79.57 149.6,79.57 149.55,79.53 147.64,79.53 146.12,78 143.16,78 142.45,78.72 133.27,78.72 132.08,79.91 124.91,79.91 v1(122.59,82.23)
  BOTTOM w0.127: v1(249.59,82.23) 249.85,81.97 U47.5 ; U45.5 122.85,81.97 v1(122.59,82.23)
_N1585: length 141.9
  L3_SIG w0.127: v1(255.09,82.75) 255.09,83.31 253.82,84.58 248.21,84.58 241.45,77.82 224.63,77.82 222.52,75.72 218.29,75.72 211.89,82.12 197.1,82.12 193.47,85.75 187.6,85.75 186.61,84.76 157.39,84.76 153.68,81.05 148.11,81.05 146.97,79.91 145.64,79.91 145.24,79.5 138.42,79.5 138.4,79.49 133.97,79.49 130.71,82.75 v1(128.09,82.75)
  BOTTOM w0.127: v1(128.09,82.75) 127.82,82.47 U45.11 ; U47.11 254.82,82.47 v1(255.09,82.75)
_N1586: length 142.7
  L3_SIG w0.127: v1(255.09,81.22) 254.3,82.01 254.3,83.01 253.21,84.1 248.41,84.1 241.76,77.44 224.75,77.44 222.67,75.36 222.55,75.36 222.5,75.31 218.06,75.31 211.73,81.64 196.67,81.64 192.91,85.39 188.04,85.39 187.05,84.4 157.54,84.4 153.83,80.7 150.22,80.7 149.45,79.93 147.49,79.93 147.11,79.55 145.85,79.55 144.65,78.36 143.31,78.36 142.59,79.07 133.65,79.07 131.5,81.22 v1(128.09,81.22)
  BOTTOM w0.127: v1(128.09,81.22) 127.85,80.97 U45.14 ; U47.14 254.85,80.97 v1(255.09,81.22)
_N1598: length 1.4
  BOTTOM w0.127: U47.15 255.51,80.47 R410.1
_N1602: length 1.4
  BOTTOM w0.127: U45.12 128.53,81.97 R403.2
_N1603: length 1.4
  BOTTOM w0.127: U45.9 128.5,83.47 R402.2
_N1604: length 1.4
  BOTTOM w0.127: R401.2 122.19,82.97 U45.7
_N1605: length 1.4
  BOTTOM w0.127: R400.2 122.17,81.47 U45.4
_N1606: length 1.4
  BOTTOM w0.127: U47.4 249.17,81.47 R412.1
_N1607: length 1.4
  BOTTOM w0.127: U47.7 249.19,82.97 R413.1
_N1608: length 1.4
  BOTTOM w0.127: U47.9 255.5,83.47 R414.1
_N1609: length 1.4
  BOTTOM w0.127: U47.12 255.53,81.97 R415.1
_N1616: length 1.4
  TOP w0.508: R429.1 DS16.C
_N1617: length 1.4
  TOP w0.508: R430.1 DS17.C
_N1618: length 1.4
  TOP w0.508: R431.1 DS18.C
_N1619: length 1.4
  TOP w0.508: R427.1 DS14.C
_N1620: length 1.4
  TOP w0.508: R428.1 DS15.C
_N1621: length 1.4
  TOP w0.508: R426.1 DS13.C
_N1696: length 78.1
  TOP w0.127: S16.8B 166,139.83 164.49,139.83 164.11,139.45 164.11,136.14 164.49,135.76 166,135.76 S16.6B 166,134.75 164.49,134.75 164.11,134.37 164.11,131.06 164.49,130.68 166,130.68 S16.4B 166,129.67 164.49,129.67 164.11,129.29 164.11,125.98 164.49,125.6 166,125.6 S16.2B v1(168.31,125.09)
  TOP w0.14: R136.1 v1(215.51,121.08)
  BOTTOM w0.127: v1(168.31,125.09) 168.95,124.46 179.44,124.46 180.07,123.83 184.77,123.83 187.52,121.08 v1(215.51,121.08)
_N1726: length 1.4
  BOTTOM w0.127: U46.15 145.02,80.47 R409.1
_N1727: length 143.1
  L3_SIG w0.127: v1(139.06,80.7) 139.88,81.52 142.06,81.52 143.73,79.86 145.08,79.86 146.63,81.41 153.53,81.41 157.32,85.19 185.33,85.19 186.28,86.14 190.33,86.14 191.1,86.91 193.33,86.91 197.69,82.55 212.09,82.55 218.57,76.07 222.38,76.07 224.51,78.21 240.92,78.21 247.75,85.04 254.28,85.04 258.62,80.7 v1(266.06,80.7)
  BOTTOM w0.127: U46.2 139.29,80.47 v1(139.06,80.7) ; U48.2 266.29,80.47 v1(266.06,80.7)
_N1728: length 144
  L3_SIG w0.127: v1(266.1,82.23) 258.23,82.23 254.91,85.55 247.6,85.55 240.61,78.56 224.28,78.56 219.82,83.02 198.16,83.02 193.92,87.26 190.95,87.26 190.19,86.5 186.13,86.5 185.18,85.55 157.17,85.55 153.41,81.79 146.51,81.79 144.93,80.21 144.25,80.21 143.59,80.88 143.59,83.11 142.67,84.02 140,84.02 139.1,83.12 v1(139.1,82.23)
  BOTTOM w0.127: U48.5 266.36,81.97 v1(266.1,82.23) ; U46.5 139.36,81.97 v1(139.1,82.23)
_N1729: length 146.9
  L3_SIG w0.127: v1(271.6,82.75) 271.6,85.78 265.1,92.28 248.43,92.28 241.75,85.6 235.64,85.6 229.67,79.63 225.25,79.63 215.39,89.48 186.85,89.48 184.41,87.05 157.05,87.05 153.7,83.69 145.55,83.69 v1(144.6,82.75)
  BOTTOM w0.127: v1(144.6,82.75) 144.33,82.47 U46.11 ; v1(271.6,82.75) 271.33,82.47 U48.11
_N1730: length 144
  L3_SIG w0.127: v1(144.6,81.22) 145.88,82.5 153.09,82.5 157.2,86.61 184.49,86.61 187,89.13 215.04,89.13 224.89,79.27 239.88,79.27 247.27,86.66 254.76,86.66 256.9,88.8 258.63,88.8 261.27,86.16 267.47,86.16 270.94,82.69 270.94,81.88 v1(271.6,81.22)
  BOTTOM w0.127: U46.14 144.36,80.97 v1(144.6,81.22) ; U48.14 271.36,80.97 v1(271.6,81.22)
_N1731: length 1.4
  BOTTOM w0.127: R411.1 272.02,80.47 U48.15
_N1732: length 1.4
  BOTTOM w0.127: R407.2 145.04,81.97 U46.12
_N1733: length 1.4
  BOTTOM w0.127: R406.2 145.01,83.47 U46.9
_N1734: length 1.4
  BOTTOM w0.127: U46.7 138.7,82.97 R405.2
_N1735: length 1.4
  BOTTOM w0.127: R404.2 138.68,81.47 U46.4
_N1736: length 1.4
  BOTTOM w0.127: R416.1 265.68,81.47 U48.4
_N1737: length 1.4
  BOTTOM w0.127: R417.1 265.7,82.97 U48.7
_N1738: length 1.4
  BOTTOM w0.127: R418.1 272.01,83.47 U48.9
_N1739: length 1.4
  BOTTOM w0.127: R419.1 272.04,81.97 U48.12
_N1774: length 1.5
  TOP w0.127: DS1.C R23.1
_N1775: length 1.5
  TOP w0.127: DS2.C R26.1
_N1776: length 1.5
  TOP w0.127: DS3.C R27.1
_N1800: length 1.5
  TOP w0.127: DS4.C R28.1
_N1801: length 1.5
  TOP w0.127: DS5.C R29.1
_N1802: length 1.5
  TOP w0.127: DS6.C R30.1
_N1808: length 3.3
  TOP w0.127: SOMB.111 v1(268.64,64.78)
  BOTTOM w0.127: v1(268.64,64.78) 268.64,62.98 R8.2
_N1810: length 1.5
  BOTTOM w0.14: U1.9 140.07,41.69 140.23,41.53 140.24,41.53 140.24,41.53 R56.2
_N1813: length 6.3
  BOTTOM w0.14: R88.1 269.35,41.53 270.82,40.07 270.82,37.91 271.16,37.57 Y2.3
_N1815: length 1.5
  BOTTOM w0.14: R88.2 267.24,41.53 267.24,41.53 267.23,41.53 267.07,41.69 U2.9
_N1851: length 4
  TOP w0.127: Y3.3 R502.1 R503.1 178.56,127.63 R126.1
_N1863: length 1.4
  TOP w0.127: U14.15 239.76,97.52 R121.1
_N1867: length 1.4
  TOP w0.127: R122.1 239.76,82.91 U15.15
_N1869: length 1.7
  TOP w0.127: R120.2 226.04,89.69 S2.1
_N1910: length 5.3
  BOTTOM w0.14: U65.A3 101.49,85.09 101.09,84.7 101.09,83.69 100.84,83.44 100.58,83.44 100.33,83.69 100.33,84.32 100.19,84.45 R39.2
_N1911: length 5.3
  BOTTOM w0.14: R37.2 103.61,89.02 103.61,88.71 103.43,88.52 102.87,88.52 102.73,88.38 102.73,88.15 102.87,88.01 103.62,88.01 103.87,87.76 103.87,86.23 104.01,86.09 U65.C2
_N1912: length 5.4
  BOTTOM w0.14: U65.C3 103.92,85.56 99.22,85.56 R41.1
_N1913: length 5.3
  BOTTOM w0.14: R43.1 105.46,81.54 105.46,81.86 105.32,82 104.31,82 104.14,82.17 104.14,82.41 104.28,82.55 104.76,82.55 104.9,82.69 104.9,83.6 U65.D4
_N1914: length 5.3
  BOTTOM w0.14: R46.1 106.18,89 106.18,88.71 106.36,88.52 106.92,88.52 107.06,88.38 107.06,88.15 106.92,88.01 106.17,88.01 105.92,87.76 105.92,86.23 105.78,86.09 U65.D2
_N1915: length 5.4
  BOTTOM w0.14: R42.1 109.32,86.61 107.67,86.61 107.53,86.47 107.53,85.69 107.32,85.48 105.78,85.48 U65.D3
_N1916: length 5.3
  BOTTOM w0.14: R38.2 99.95,88.27 101.09,87.12 102.36,87.12 U65.B2
_N1917: length 5.3
  BOTTOM w0.14: U65.E1 106.65,87.09 108.33,88.77 108.97,88.77 109.11,88.91 109.11,89.11 108.97,89.25 R49.1
_N1918: length 5.2
  BOTTOM w0.14: R44.1 106.05,81.65 106.18,81.79 107.47,81.79 107.61,81.93 107.61,82.25 107.44,82.42 106.06,82.42 U65.D5
_N1919: length 5.4
  BOTTOM w0.14: U65.E3 106.65,84.84 107.68,84.84 108.08,85.23 108.08,85.97 108.22,86.11 108.57,86.11 108.71,85.97 108.71,85.09 108.89,84.91 109.34,84.91 R48.1
_N1920: length 5.2
  BOTTOM w0.14: R47.1 103.76,81.65 103.62,81.79 102.87,81.79 102.62,82.04 102.62,82.42 102.87,82.68 103.63,82.68 103.89,82.93 103.89,83.58 U65.C4
_N1921: length 5.3
  BOTTOM w0.14: R45.1 109.35,87.21 109.02,87.21 108.88,87.35 108.88,88 108.74,88.14 108.46,88.14 108.32,88 108.32,87.35 108.18,87.21 107.51,87.21 U65.E2
_N1922: length 5.3
  BOTTOM w0.14: R40.2 102.36,89.12 102.36,88.28 102.08,88 101.23,88 101.12,87.89 101.12,87.69 101.26,87.55 103.2,87.55 103.39,87.36 U65.B1
_N1956: length 2.4
  TOP w0.127: P30.15 R516.1
_N1957: length 1.7
  TOP w0.127: DS21.A 62.82,91.56 R516.2
_N1976: length 2.4
  TOP w0.127: P31.15 R519.1
_N1977: length 1.7
  TOP w0.127: R519.2 378.16,91.56 DS22.A
_N1980: length 3.5
  TOP w0.127: R518.1 R517.2 P31.6
_N1981: length 3.5
  TOP w0.127: P30.6 R514.2 R515.1
_N2048: length 1.4
  BOTTOM w0.127: R524.1 136.89,88.6 U61.15
_N2049: length 157.1
  TOP w0.127: v1(133.21,88.6) 134.45,88.6 135.38,89.54 135.38,91.06 137.54,93.22 137.54,97.26 144.48,104.19 166.32,104.19 174.5,96.01 200.75,96.01 203.85,99.11 236.4,99.11 238.68,101.4 257.02,101.4 261.49,96.93 261.49,91.69 260.48,90.68 v1(260.48,88.6)
  BOTTOM w0.127: U61.2 v1(133.21,88.6) ; U62.2 v1(260.48,88.6)
_N2050: length 156
  TOP w0.127: v1(261.24,90.1) 262.13,90.99 262.13,97.18 257.02,102.29 238.58,102.29 235.84,99.54 202.79,99.54 199.72,96.47 174.91,96.47 166.73,104.65 144.2,104.65 136.91,97.36 136.91,93.79 v1(133.21,90.1)
  BOTTOM w0.127: U61.5 v1(133.21,90.1) ; U62.5 v1(261.24,90.1)
_N2053: length 1.4
  BOTTOM w0.127: U62.15 263.89,88.6 R525.1
_N2056: length 1.4
  BOTTOM w0.127: U61.7 130.57,91.1 R521.2
_N2057: length 1.4
  BOTTOM w0.127: U61.4 130.55,89.6 R520.2
_N2058: length 1.4
  BOTTOM w0.127: R526.1 257.55,89.6 U62.4
_N2059: length 1.4
  BOTTOM w0.127: U62.7 257.57,91.1 R527.1
_N2133: length 2.7
  TOP w0.127: R552.1 225.23,28.5 226.05,29.32 226.05,29.72 225.32,30.45 DS23.C
_N2134: length 1.3
  TOP w0.127: U66.3 R549.2
_N2135: length 1.5
  TOP w0.127: U66.6 234.03,28.37 R550.1
_N2136: length 9.3
  TOP w0.127: U66.2 237.61,27.87 237.97,27.51 238.66,27.51 241.36,24.8 v1(241.36,23.45)
  BOTTOM w0.127: R548.2 U64.4
  BOTTOM w0.14: R548.2 v1(241.36,23.45)
_N2137: length 1.5
  TOP w0.127: C395.1 233.9,27.87 U66.7
_N2144: length 1.8
  TOP w0.127: DS24.A 131.75,89.1 v1(132.71,89.1)
  BOTTOM w0.127: U61.3 v1(132.71,89.1)
_N2145: length 1.8
  TOP w0.127: v1(132.71,90.6) 131.75,90.6 DS19.A
  BOTTOM w0.127: U61.6 v1(132.71,90.6)
_N2146: length 1.8
  TOP w0.127: DS25.A 258.75,89.1 v1(259.71,89.1)
  BOTTOM w0.127: U62.3 v1(259.71,89.1)
_N2147: length 1.8
  TOP w0.127: DS26.A 258.75,90.6 v1(259.71,90.6)
  BOTTOM w0.127: U62.6 v1(259.71,90.6)
_N2150: length 1.4
  TOP w0.127: R449.1 DS19.C
_N2154: length 1.4
  TOP w0.127: DS24.C R450.1
_N2157: length 1.4
  TOP w0.127: DS25.C R457.1
_N2160: length 1.4
  TOP w0.127: R458.1 DS26.C
_N2166: length 1.7
  TOP w0.127: R462.2 219.06,89.56 S1.1
_N2171: length 1.4
  TOP w0.127: U52.15 239.76,90.02 R522.1
_N2179: length 3.2
  TOP w0.14: P8.1 207.77,70.79 R531.2
_N2180: length 2.7
  TOP w0.14: R532.2 202.68,66.35 P8.10
_N2192: length 1.4
  BOTTOM w0.14: U67.15 10.93,32.62 R533.1
_N2202: length 1.4
  BOTTOM w0.14: U69.15 378.6,32.62 R534.1
_N2225: length 5.9
  TOP w0.14: 35.43,22.61 35.43,20.59 R565.1 ; R565.1 R267.2 ; R565.1 35.22,18.7 C167.1
_N2226: length 5.9
  TOP w0.14: 36.7,22.61 36.7,20.59 R565.2 ; R565.2 36.92,18.7 C384.1 ; R565.2 R564.1
_N2229: length 3.9
  TOP w0.14: J1.T2 C167.2
_N2232: length 1.6
  TOP w0.14: C386.1 27.3,21.95 U71.4
_N2233: length 1.3
  TOP w0.14: C386.2 R566.1
_N2248: length 5.9
  TOP w0.14: R570.1 R568.2 ; R570.1 403.1,20.59 403.1,22.61 ; R570.1 402.88,18.7 C391.1
_N2249: length 5.9
  TOP w0.14: R570.2 404.37,20.59 404.37,22.61 ; R570.2 404.58,18.7 C392.1 ; R570.2 R569.1
_N2251: length 3.9
  TOP w0.14: J2.T2 C391.2
_N2252: length 1.6
  TOP w0.14: U73.4 394.97,21.95 C397.1
_N2253: length 1.3
  TOP w0.14: C397.2 R571.1
_N2262: length 8.1
  TOP w0.14: v1(15.24,24) 14.75,23.51 U63.2
  TOP w0.203: R573.2 v1(20.45,26.29)
  BOTTOM w0.14: v1(15.24,24) 17.53,26.29 v1(20.45,26.29)
_N2263: length 9.7
  TOP w0.14: U63.3 14.35,24.13 v1(14.73,24.51)
  TOP w0.203: R574.2 v1(20.45,28.19)
  BOTTOM w0.14: v1(14.73,24.51) 15.11,24.51 18.8,28.19 v1(20.45,28.19)
_N2264: length 8.3
  TOP w0.14: v1(13.08,24) 13.55,23.53 U63.5 ; R576.2 v1(8,26.92)
  BOTTOM w0.14: v1(8,26.92) 10.16,26.92 v1(13.08,24)
_N2265: length 9.9
  TOP w0.14: v1(13.59,24.51) 13.95,24.15 U63.4 ; R575.2 v1(8,28.96)
  BOTTOM w0.14: v1(8,28.96) 8.76,28.96 13.21,24.51 v1(13.59,24.51)
_N2272: length 3.5
  TOP w0.203: R577.2 97.92,115.19 98.87,116.14 U33.19
_N2408: length 8.1
  TOP w0.14: U68.2 382.42,23.51 v1(382.91,24)
  TOP w0.203: R578.2 v1(388.12,26.29)
  BOTTOM w0.14: v1(388.12,26.29) 385.19,26.29 v1(382.91,24)
_N2409: length 9.9
  TOP w0.14: v1(381.25,24.51) 381.62,24.15 U68.4 ; R580.2 v1(375.66,28.96)
  BOTTOM w0.14: v1(375.66,28.96) 376.43,28.96 380.87,24.51 v1(381.25,24.51)
_N2414: length 8.3
  TOP w0.14: v1(380.75,24) 381.22,23.53 U68.5 ; R581.2 v1(375.66,26.92)
  BOTTOM w0.14: v1(380.75,24) 377.82,26.92 v1(375.66,26.92)
_N2415: length 9.7
  TOP w0.14: U68.3 382.02,24.13 v1(382.4,24.51)
  TOP w0.203: R579.2 v1(388.12,28.19)
  BOTTOM w0.14: v1(388.12,28.19) 386.46,28.19 382.78,24.51 v1(382.4,24.51)
_N2416: length 2.2
  TOP w0.305: 371.48,168.91 R461.1
_N2417: length 2.2
  TOP w0.305: P17.1 R460.1
_N2430: length 2.2
  TOP w0.14: R582.2 229.72,110.08 U17.2
_N2436: length 69.2
  TOP w0.127: v1(176.92,140.34) S16.8A S16.7A
  TOP w0.14: v1(229.23,113.03) 229.72,112.54 U17.10
  BOTTOM w0.127: v1(176.92,140.34) 195.64,121.62 215.94,121.62 216.4,121.16 217.17,121.16 224.16,114.17 228.09,114.17 v1(229.23,113.03)
_N2437: length 168.8
  TOP w0.127: v1(164.71,122.43) 166.38,122.43 S16.1B 167.02,123.06 168.53,123.06 168.91,123.44 168.91,126.75 168.53,127.13 167.02,127.13 S16.3B 167.02,128.14 168.53,128.14 168.91,128.52 168.91,131.83 168.53,132.21 167.02,132.21 S16.5B 167.02,133.22 168.53,133.22 168.91,133.6 168.91,136.91 168.53,137.29 167.02,137.29 S16.7B
  TOP w0.14: R135.1 v1(293.24,121.08)
  BOTTOM w0.127: v1(293.24,121.08) 287.32,121.08 283.41,124.99 248.67,124.99 236.12,112.45 227.43,112.45 226.97,112.9 224.64,112.9 218.29,119.25 186.55,119.25 183.38,122.43 v1(164.71,122.43)
_N2439: length 151.3
  TOP w0.127: S16.1A S16.2A v1(176.92,125.09)
  TOP w0.14: U16.10 307.45,112.54 v1(306.96,113.03)
  L8_SIG w0.127: v1(306.96,113.03) 306.91,113.03 306.3,112.42 304.68,112.42 304.28,112.81 303.83,112.81 303.44,112.42 302.46,112.42 300.51,114.38 275.13,114.38 265.1,124.41 242.65,124.41 233.1,114.86 183.83,114.86 176.92,121.77 v1(176.92,125.09)
_N2453: length 4.8
  TOP w0.14: R583.1 R584.1 204.63,76.9 P35.10
_N2454: length 3.4
  TOP w0.14: P35.1 210.84,79.32 R585.2
_N2460: length 2.5
  TOP w0.127: SOMA.274 182.4,75.99 R586.1
_N2463: length 2.5
  TOP w0.127: SOMB.274 R587.1
_N2470: length 11.9
  TOP w0.14: v1(15.74,27.57) 15.14,27.57 14.94,27.37 14.94,26.21 15.53,25.62 U74.2
  TOP w0.203: U74.5 v1(15.74,27.57)
  BOTTOM w0.14: v1(15.74,27.57) 15.04,28.26 15.04,32.42 15.24,32.62 U67.2
_N2471: length 9.1
  TOP w0.14: U74.9 v1(13.22,28.22) 13.59,27.85 13.59,26.8 13.06,26.27 U74.12
  BOTTOM w0.14: U67.11 13.02,30.62 13.22,30.42 v1(13.22,28.22)
_N2476: length 1.6
  TOP w0.203: U74.3 18.66,26.27 R573.1
_N2477: length 1.6
  TOP w0.203: U74.6 17.12,28.19 R574.1
_N2478: length 1.6
  TOP w0.14: U74.8 9.86,28.87 R575.1
_N2479: length 1.6
  TOP w0.14: R576.1 9.78,26.92 U74.11
_N2500: length 11.9
  TOP w0.14: v1(383.4,27.57) 382.81,27.57 382.6,27.37 382.6,26.21 383.19,25.62 U75.2
  TOP w0.203: U75.5 v1(383.4,27.57)
  BOTTOM w0.14: U69.2 382.91,32.62 382.71,32.42 382.71,28.26 v1(383.4,27.57)
_N2501: length 9.1
  TOP w0.14: U75.9 v1(380.89,28.22) 381.25,27.85 381.25,26.8 380.73,26.27 U75.12
  BOTTOM w0.14: U69.11 380.68,30.62 380.89,30.42 v1(380.89,28.22)
_N2502: length 1.6
  TOP w0.203: U75.3 386.32,26.27 R578.1
_N2503: length 1.6
  TOP w0.203: R579.1 384.78,28.19 U75.6
_N2504: length 1.6
  TOP w0.14: R580.1 377.52,28.87 U75.8
_N2505: length 1.6
  TOP w0.14: R581.1 377.44,26.92 U75.11
_N2535: length 3.5
  BOTTOM w0.305: C418.1 98.3,58.5 98.6,58.81 U77.7
